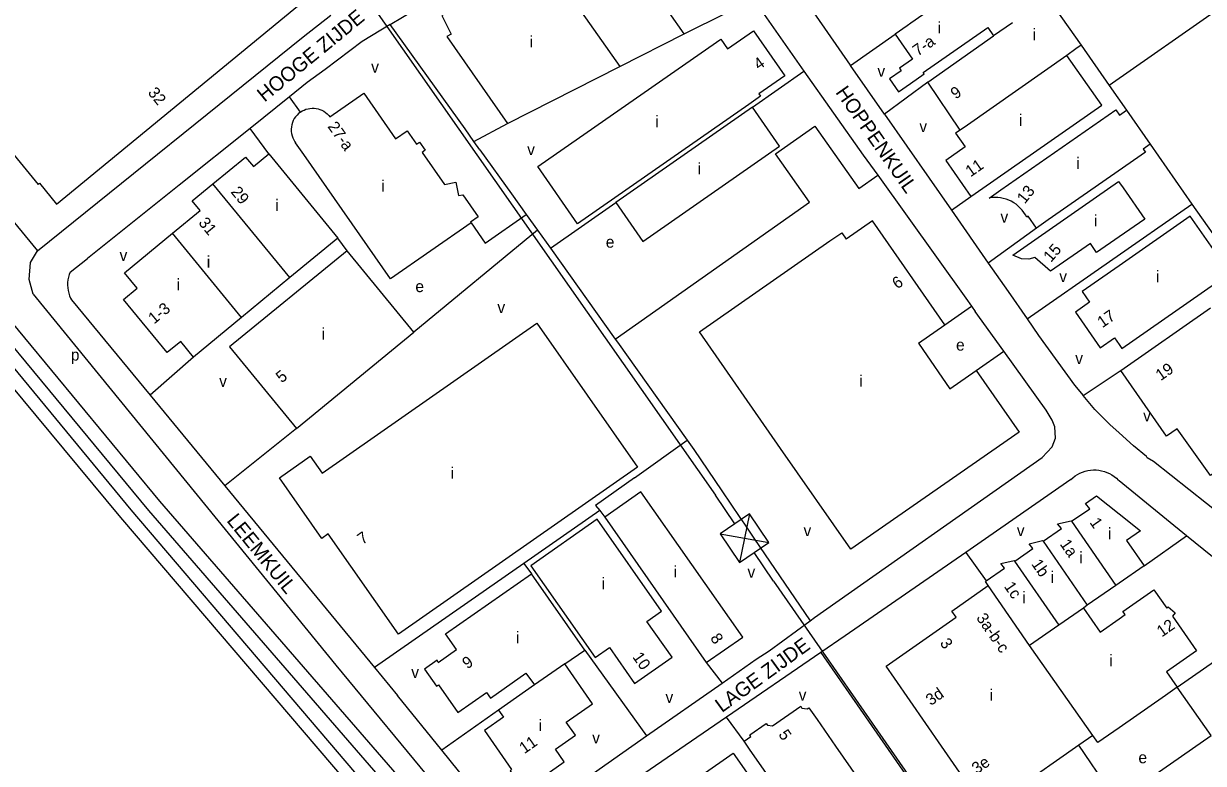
# Model space of a CAD drawing. Extents: x 156721 to 158827, y 386657 to 388950.
# Drawn here: x 156928.2 to 157336.1, y 387994 to 388249.8 of the extents above; entities that cross this region are included whole.
import ezdxf

# ---------------------------------------------------------------- set-up
doc = ezdxf.new("R2010")
doc.units = 0
for name, color, linetype in [('BLT_Basislijn', 7, 'Continuous'), ('BLT_Bebouwing', 7, 'Continuous'), ('BLT_Centroide', 7, 'Continuous'), ('BLT_Hoogspanningsmast_en_leidingen', 7, 'Continuous'), ('BLT_Huisnummer', 7, 'Continuous'), ('BLT_Huisnummer_reeks', 7, 'Continuous'), ('BLT_Onderverdeling_panden', 7, 'Continuous'), ('BLT_Spoorlijn', 7, 'Continuous'), ('BLT_Straatnaam', 7, 'Continuous')]:
    doc.layers.add(name, color=color, linetype=linetype)

msp = doc.modelspace()

# ---------------------------------------------------------------- linework, layer by layer
at = {"layer": 'BLT_Basislijn'}
for p, q in [((157181.81, 388256.38), (157197.97, 388233.43)), ((157342.19, 388255.43), (157303.53, 388228.38)), ((157156.54, 388246.26), (157171.21, 388253.53)), ((157214.08, 388235.38), (157229.53, 388246.22)), ((157293.8, 388242.31), (157303.53, 388228.38)), ((157225.82, 388218.52), (157214.08, 388235.38)), ((157180.18, 388220.88), (157197.97, 388233.43)), ((157197.97, 388233.43), (157218.52, 388204.37)), ((157240.87, 388229.61), (157225.82, 388218.52)), ((157303.53, 388228.38), (157309.5, 388219.84)), ((157020.19, 388224.52), (157006.55, 388213.59)), ((157023.9, 388219.23), (157020.19, 388224.52)), ((157083.93, 388209.08), (157095.54, 388215.31)), ((157225.82, 388218.52), (157248.98, 388185.32)), ((157006.55, 388213.59), (156982.02, 388193.93)), ((157012.98, 388204.79), (157006.55, 388213.59)), ((157085.98, 388206.23), (157083.93, 388209.08)), ((157317.68, 388208.11), (157332.16, 388187.41)), ((156904.22, 388206.2), (156933, 388171.26)), ((157085.98, 388206.23), (157096.92, 388190.96)), ((156882.19, 388197.04), (156975.19, 388084.73)), ((156982.02, 388193.93), (156950.34, 388168.56)), ((157096.92, 388190.96), (157102, 388183.86)), ((157248.98, 388185.32), (157255.75, 388190.07)), ((157110.34, 388172.18), (157132.95, 388187.99)), ((157275.16, 388147.74), (157332.16, 388187.41)), ((157332.16, 388187.41), (157351.14, 388160.27)), ((157102, 388183.86), (157105.89, 388178.43)), ((157248.98, 388185.32), (157261.74, 388167.03)), ((157105.89, 388178.43), (157063.13, 388143.09)), ((157105.89, 388178.43), (157110.34, 388172.18)), ((157278.39, 388179.09), (157261.74, 388167.03)), ((157040.03, 388171.28), (157036.9, 388175.64)), ((157110.34, 388172.18), (157132.77, 388140.76)), ((156944.29, 388163.93), (156950.34, 388168.56)), ((156931.5, 388156.24), (156995.39, 388077.95)), ((156944.73, 388154.35), (156971.92, 388121.35)), ((157246.71, 388145.66), (157255.9, 388152.1)), ((156986.97, 388134.54), (156971.92, 388121.35)), ((157257.58, 388129.9), (157267.08, 388136.5)), ((157294.55, 388121.21), (157306.95, 388129.58)), ((157306.95, 388129.58), (157307.54, 388129.89)), ((156971.92, 388121.35), (156997.81, 388089.95)), ((157022.55, 388109.84), (156997.81, 388089.95)), ((157139.45, 388092.71), (157157.63, 388105.84)), ((157139.45, 388092.71), (157125.94, 388083.22)), ((157290.3, 388092.17), (157253.94, 388066.99)), ((156997.81, 388089.95), (157049.56, 388027.17)), ((157169.66, 388088.25), (157175.89, 388079.07)), ((157306.95, 388091.75), (157306.68, 388091.97)), ((157330.23, 388072.76), (157306.95, 388091.75)), ((157127.41, 388081.49), (157101.18, 388063.19)), ((157125.94, 388083.22), (157127.41, 388081.49)), ((157127.41, 388081.49), (157129.11, 388079.17)), ((156995.39, 388077.95), (157036.15, 388028.01)), ((157175.89, 388079.07), (157177.49, 388076.7)), ((157177.49, 388076.7), (157180.71, 388071.95)), ((157180.71, 388071.95), (157182.66, 388069.07)), ((157315.6, 388062.38), (157330.23, 388072.76)), ((157353.28, 388053.95), (157330.23, 388072.76)), ((157182.66, 388069.07), (157200.14, 388043.27)), ((157253.94, 388066.99), (157212.31, 388038.16)), ((157253.94, 388066.99), (157261.02, 388057.14)), ((157101.18, 388063.19), (157049.56, 388027.17)), ((157101.18, 388063.19), (157103.8, 388059.53)), ((157327.07, 388020.36), (157362.69, 388045.37)), ((157212.31, 388038.16), (157203.8, 388032.33)), ((157122.2, 388033.18), (157143.6, 388003.53)), ((157203.8, 388032.33), (157171.21, 388010.02)), ((157203.8, 388032.33), (157240.15, 387980.09)), ((157036.15, 388028.01), (157169.06, 387867.32)), ((157049.56, 388027.17), (157057.48, 388017.55)), ((157164.2, 388028.86), (157169.69, 388021.79)), ((157143.6, 388003.53), (157169.69, 388021.79)), ((157338.76, 388003.71), (157327.07, 388020.36)), ((157072.83, 387998.56), (157057.48, 388017.55)), ((157092.39, 388012.46), (157072.83, 387998.56)), ((157171.21, 388010.02), (157109.44, 387967.74)), ((157177.3, 388001.69), (157171.21, 388010.02)), ((157104.5, 387976.17), (157143.6, 388003.53)), ((157090.57, 387976.6), (157072.83, 387998.56))]:
    msp.add_line(p, q, dxfattribs=at)
for points in [[(157054.94, 388249.56), (157067.74, 388257.09), (157078.57, 388262.26), (157088.23, 388267.49), (157145.85, 388296.83), (157148.06, 388297.3), (157150.99, 388297.47), (157153.2, 388296.54), (157155.52, 388294.2), (157180.29, 388258.56)], [(157197.86, 388258.78), (157198.32, 388258.14), (157213.99, 388235.5), (157214.08, 388235.38)], [(156933, 388171.26), (157024.89, 388245.27), (157034.44, 388252.69)], [(157054.94, 388249.56), (157045.3, 388243.68), (157032.46, 388233.97), (157026.3, 388229.42), (157020.19, 388224.52)], [(157083.93, 388209.08), (157080.85, 388213.38), (157054.94, 388249.56)], [(157132.77, 388140.76), (157199.97, 388188.11), (157188.21, 388204.81), (157201.78, 388214.37), (157216.99, 388192.78), (157223.52, 388197.38)], [(157218.52, 388204.37), (157223.52, 388197.38)], [(157223.52, 388197.38), (157253.92, 388154.87), (157255.9, 388152.1)], [(157082.92, 388180.95), (157087.8, 388173.95), (157102, 388183.86)], [(156931.5, 388156.24), (156930.1, 388161.39), (156930.61, 388167.25), (156933, 388171.26)], [(157261.74, 388167.03), (157268.62, 388157.17), (157275.16, 388147.74)], [(156944.29, 388163.93), (156943.96, 388163.06), (156943.7, 388162.16), (156943.52, 388161.25), (156943.41, 388160.32), (156943.39, 388159.39), (156943.45, 388158.45), (156943.58, 388157.53), (156943.8, 388156.62), (156944.09, 388155.74), (156944.46, 388154.88), (156944.73, 388154.35)], [(157255.9, 388152.1), (157257.24, 388150.23)], [(157267.08, 388136.5), (157257.24, 388150.23)], [(157275.16, 388147.74), (157279.15, 388141.99), (157291.59, 388124.77), (157294.55, 388121.21)], [(157132.77, 388140.76), (157133.55, 388139.69), (157157.63, 388105.84)], [(157200.14, 388043.27), (157201.7, 388044.41), (157280.41, 388099.77), (157283.84, 388103.46), (157284.96, 388106.42), (157284.8, 388110.41), (157283.78, 388112.74), (157281.7, 388116.1), (157267.08, 388136.5)], [(157306.95, 388108.35), (157303.79, 388111.21), (157298.56, 388116.38), (157294.55, 388121.21)], [(157157.63, 388105.84), (157159.96, 388102.56), (157169.66, 388088.25)], [(157343.34, 388079.1), (157318.8, 388098.44), (157316.67, 388099.68), (157316.49, 388100.1), (157311.93, 388103.84), (157306.95, 388108.35)], [(157290.3, 388092.17), (157291.01, 388092.81), (157291.78, 388093.4), (157292.58, 388093.91), (157293.43, 388094.36), (157294.32, 388094.74), (157295.23, 388095.04), (157296.16, 388095.27), (157297.11, 388095.41), (157298.07, 388095.48), (157299.03, 388095.47), (157299.98, 388095.38), (157300.93, 388095.2), (157301.86, 388094.95), (157302.76, 388094.63), (157303.63, 388094.23), (157304.47, 388093.76), (157305.26, 388093.22), (157306.01, 388092.61), (157306.68, 388091.97)], [(156975.19, 388084.73), (157094.16, 387947.52), (157166.18, 387865.29)], [(157169.69, 388021.79), (157181.46, 388030.1), (157185.99, 388032.98), (157200.14, 388043.27)]]:
    msp.add_lwpolyline(points, dxfattribs=at)
at = {"layer": 'BLT_Bebouwing'}
for p, q in [((157156.54, 388246.26), (157151.41, 388253.67)), ((157074.56, 388245.32), (157095.54, 388215.31)), ((157134.3, 388234.97), (157156.54, 388246.26)), ((157240.87, 388229.61), (157263.58, 388245.55)), ((157292.06, 388241.06), (157288.94, 388238.83)), ((157095.54, 388215.31), (157134.3, 388234.97)), ((157300.96, 388221.65), (157288.94, 388238.83)), ((157252.03, 388213.02), (157240.87, 388229.61)), ((157012.98, 388204.79), (157036.9, 388175.64)), ((156933.68, 388194.59), (156939.56, 388187.44)), ((157270.21, 388169.74), (157306.79, 388195.19)), ((157306.79, 388195.19), (157308.33, 388192.98)), ((157331.5, 388183.23), (157306.95, 388166.09)), ((157345.25, 388163.53), (157331.5, 388183.23)), ((157036.9, 388175.64), (157020.3, 388161.98)), ((157063.13, 388143.09), (157040.03, 388171.28)), ((157306.95, 388166.09), (157294.19, 388157.18)), ((157020.3, 388161.98), (157003.59, 388148.22)), ((157307.54, 388129.89), (157338.61, 388151.54)), ((157022.55, 388109.84), (157063.13, 388143.09)), ((157237.62, 388139.3), (157239.12, 388137.14)), ((157122.2, 388033.18), (157103.8, 388059.53)), ((157315.6, 388062.38), (157306.95, 388056.35)), ((157305.84, 388055.57), (157295.98, 388048.69)), ((157306.95, 388056.35), (157305.84, 388055.57)), ((157295.98, 388048.69), (157294.62, 388047.74)), ((157115.33, 388028.48), (157122.2, 388033.18)), ((157104.83, 388021.14), (157092.39, 388012.46)), ((157297.94, 388003.66), (157293.07, 388000.27)), ((157299.62, 388001.23), (157297.94, 388003.66)), ((157306.95, 388006.35), (157299.62, 388001.23)), ((157306.15, 387981), (157338.76, 388003.71)), ((157306.15, 387981), (157293.07, 388000.27))]:
    msp.add_line(p, q, dxfattribs=at)
for points in [[(156939.56, 388187.44), (157028.11, 388260.24), (157022.23, 388267.38), (157022.66, 388267.73)], [(157113.32, 388264.95), (157106.8, 388261.68), (157103.55, 388268.11), (157089.99, 388261.26), (157089.63, 388261.95), (157084.48, 388259.33), (157084.8, 388258.65), (157072.86, 388252.59), (157076.09, 388246.18), (157074.56, 388245.32)], [(157258.66, 388266.55), (157234.95, 388250), (157233.64, 388249.08), (157229.53, 388246.22)], [(157282.34, 388258.71), (157293.8, 388242.31)], [(157171.55, 388241.12), (157180.54, 388247.36), (157191.37, 388231.8), (157182.4, 388225.55)], [(157229.53, 388246.22), (157235.57, 388237.57), (157231.01, 388234.39), (157231.64, 388233.49), (157227.61, 388230.68), (157230.68, 388226.28), (157234.79, 388229.14), (157239.53, 388232.45), (157239.24, 388232.88), (157261.55, 388248.45), (157263.58, 388245.55)], [(157182.4, 388225.55), (157183.01, 388224.68), (157178.91, 388221.83), (157119.75, 388180.62), (157106, 388200.43), (157165.12, 388241.59), (157169.23, 388244.45), (157171.55, 388241.12)], [(157293.8, 388242.31), (157292.06, 388241.06)], [(157023.9, 388219.23), (157024.5, 388219.61), (157025.16, 388219.94), (157025.83, 388220.2), (157026.56, 388220.4), (157027.22, 388220.51), (157027.94, 388220.57), (157028.66, 388220.56), (157029.36, 388220.48), (157030.02, 388220.34), (157030.68, 388220.13), (157031.34, 388219.85), (157032, 388219.5), (157032.64, 388219.05), (157033.18, 388218.6), (157033.7, 388218.07), (157034.12, 388217.54), (157045.89, 388225.77), (157056.84, 388209.99), (157060.79, 388212.75), (157064.01, 388208.1), (157065.11, 388208.84), (157067.05, 388206.07), (157065.97, 388205.3), (157073.69, 388194.21), (157077.63, 388194.97), (157078.6, 388190.34), (157080.11, 388190.65), (157085.4, 388183.05), (157082.74, 388181.2), (157082.92, 388180.95)], [(157023.9, 388219.23), (157023.3, 388218.75), (157022.74, 388218.21), (157022.24, 388217.62), (157021.81, 388216.98), (157021.45, 388216.3), (157021.15, 388215.58), (157020.94, 388214.84), (157020.8, 388214.08), (157020.74, 388213.3), (157020.76, 388212.53), (157020.86, 388211.77), (157021.03, 388211.01), (157021.29, 388210.28), (157021.62, 388209.58), (157022.02, 388208.92), (157022.22, 388208.64)], [(157180.18, 388220.88), (157132.95, 388187.99)], [(157132.95, 388187.99), (157142.35, 388174.51), (157189.57, 388207.4), (157180.18, 388220.88)], [(157255.75, 388190.07), (157259.85, 388192.94), (157300.96, 388221.65)], [(157261.99, 388189.49), (157266.09, 388192.36), (157305.78, 388220.06), (157307.1, 388218.17), (157309.5, 388219.84)], [(157309.5, 388219.84), (157317.68, 388208.11)], [(156917.02, 388213.95), (156933.23, 388194.21), (156933.68, 388194.59)], [(157252.03, 388213.02), (157250.42, 388211.89), (157253.75, 388207.23), (157247.04, 388202.52), (157255.75, 388190.07)], [(157082.92, 388180.95), (157055.08, 388161.53), (157025.09, 388204.54), (157022.22, 388208.64)], [(157317.68, 388208.11), (157315.29, 388206.44), (157316.06, 388205.33), (157282.49, 388181.95), (157278.39, 388179.09)], [(156993.67, 388194.38), (157004.93, 388203.66), (157007.67, 388200.39), (157012.98, 388204.79)], [(156986.54, 388188.5), (156993.67, 388194.38)], [(157308.33, 388192.98), (157315.81, 388182.24), (157306.95, 388176.08)], [(156979.68, 388177.35), (156989.23, 388185.22), (156986.54, 388188.5)], [(157275.02, 388182.86), (157274.57, 388183.73), (157274.05, 388184.55), (157273.46, 388185.33), (157272.81, 388186.06), (157272.1, 388186.74), (157271.34, 388187.35), (157270.53, 388187.9), (157269.68, 388188.38), (157268.79, 388188.79), (157267.87, 388189.13), (157266.93, 388189.39), (157265.97, 388189.57), (157264.99, 388189.68), (157264.02, 388189.7), (157263.04, 388189.64), (157262.07, 388189.51), (157261.99, 388189.49)], [(157278.39, 388179.09), (157275.52, 388183.21), (157275.02, 388182.86)], [(157246.71, 388145.66), (157221.69, 388181.58), (157212.64, 388175.28)], [(156986.97, 388134.54), (156982.6, 388139.89), (156977.9, 388136.05), (156962.78, 388154.47), (156967.47, 388158.3), (156963.06, 388163.66), (156979.68, 388177.35)], [(157189.94, 388102.89), (157161.84, 388143.24), (157206.97, 388174.67), (157211.08, 388177.53), (157212.64, 388175.28)], [(157306.95, 388176.08), (157299.2, 388170.68), (157297.02, 388173.8), (157283.26, 388164.17), (157277.84, 388168.99), (157275.81, 388168.34), (157273.27, 388168.48), (157270.21, 388169.74)], [(157040.03, 388171.28), (156999.45, 388138.02), (157022.55, 388109.84)], [(157306.95, 388138.91), (157307.95, 388137.49), (157345.25, 388163.53)], [(157294.19, 388157.18), (157296.77, 388153.49), (157291.85, 388150.06), (157300.45, 388137.74), (157305.37, 388141.18), (157306.95, 388138.91)], [(157003.59, 388148.22), (156986.97, 388134.54)], [(157027.33, 388100.26), (157031.45, 388094.36), (157105.65, 388146.19), (157140.44, 388096.39), (157057.84, 388038.7), (157033.56, 388073.34), (157031.35, 388071.79), (157016.65, 388092.76), (157027.33, 388100.26)], [(157237.62, 388139.3), (157246.71, 388145.66)], [(157239.12, 388137.14), (157248.5, 388123.59), (157257.58, 388129.9)], [(157257.58, 388129.9), (157272.43, 388108.58), (157214.23, 388068.1), (157189.94, 388102.89)], [(157356.43, 388106.06), (157338.52, 388093.57), (157327.06, 388109.73), (157323.39, 388107.18), (157307.54, 388129.89)], [(157164.2, 388028.86), (157176.83, 388037.68), (157141.58, 388087.88), (157129.11, 388079.17)], [(157290.54, 388077.72), (157296.83, 388082.08), (157295.29, 388083.86), (157299.13, 388086.55), (157306.95, 388080.36)], [(157306.95, 388080.36), (157314.38, 388074.48), (157309.55, 388071.08), (157315.6, 388062.38)], [(157125.78, 388030.63), (157130.79, 388034.14), (157139.41, 388021.65), (157152.49, 388030.77), (157143.7, 388043.14), (157148.72, 388046.64), (157126.48, 388078.49), (157103.62, 388062.29)], [(157129.11, 388079.17), (157164.2, 388028.86)], [(157280.68, 388070.85), (157287, 388075.21), (157285.7, 388076.8), (157290.35, 388077.92), (157290.54, 388077.72)], [(157270.87, 388063.99), (157277.17, 388068.37), (157275.86, 388069.93), (157280.52, 388071.05), (157280.68, 388070.85)], [(157261.02, 388057.14), (157267.31, 388061.49), (157266.03, 388063.11), (157270.67, 388064.2), (157270.87, 388063.99)], [(157071.59, 388028.95), (157077.83, 388033.35), (157074.04, 388038.77), (157103.8, 388059.53)], [(157103.62, 388062.29), (157125.78, 388030.63)], [(157260.93, 387977.89), (157245.61, 388000), (157229.3, 388023.54), (157226.45, 388027.65), (157250.63, 388044.54), (157249.11, 388046.71), (157261.73, 388055.53)], [(157261.73, 388055.53), (157260.74, 388056.95), (157261.02, 388057.14)], [(157306.95, 388044), (157309.05, 388045.45), (157308.29, 388046.54), (157319.03, 388054.03), (157323.48, 388047.64), (157323.93, 388048.17), (157326.37, 388046.1), (157325.37, 388044.92), (157333.72, 388032.92), (157323.35, 388025.66), (157327.07, 388020.36)], [(157294.62, 388047.74), (157300.38, 388039.44), (157306.95, 388044)], [(157071.59, 388028.95), (157071.18, 388029.7), (157066.8, 388026.64), (157070.92, 388020.72), (157071.61, 388021.2)], [(157115.85, 388008.3), (157124.89, 388014.58), (157115.33, 388028.48)], [(157071.61, 388021.2), (157078.35, 388011.59), (157088.23, 388018.51), (157089.58, 388016.59), (157101.85, 388025.19), (157104.83, 388021.14)], [(157327.07, 388020.36), (157322.97, 388017.51), (157306.95, 388006.35)], [(157092.39, 388012.46), (157094.11, 388009.99), (157087.55, 388005.42), (157096.89, 387991.93), (157096.38, 387991.5), (157101.36, 387984.23), (157101.56, 387984.19), (157108.81, 387989.27), (157108.4, 387989.85), (157115.14, 387994.59), (157112.1, 387998.97), (157119.01, 388003.77), (157115.85, 388008.3)], [(157177.3, 388001.69), (157179.69, 388003.34), (157179.28, 388003.91), (157184.93, 388007.86), (157185.35, 388007.27), (157187.15, 388006.98), (157196.91, 388013.77), (157197.32, 388013.14), (157199.1, 388012.91), (157199.69, 388013.26), (157202.55, 388009.16)], [(157202.55, 388009.16), (157208.92, 388000), (157219.55, 387984.74), (157223.61, 387987.58), (157232.26, 387975.15)], [(157207.74, 387957.97), (157179.18, 387998.98), (157178.48, 388000), (157177.3, 388001.69)]]:
    msp.add_lwpolyline(points, dxfattribs=at)
msp.add_lwpolyline([(157173.58, 387997.58), (157186.78, 387978.67), (157162.4, 387961.64), (157175.57, 387942.78), (157155.62, 387928.88), (157138.87, 387952.87), (157132.32, 387948.3), (157121.58, 387963.7), (157128.3, 387968.4), (157129.48, 387966.8)], close=True, dxfattribs=at)
at = {"layer": 'BLT_Hoogspanningsmast_en_leidingen'}
for p, q in [((157043.67, 388263.27), (157167.45, 388086.75)), ((157174.11, 388076.84), (157167.45, 388086.75)), ((157179.22, 388080.28), (157175.67, 388063.5)), ((157169.01, 388073.41), (157185.89, 388070.38)), ((157187.44, 388057.04), (157180.78, 388066.94)), ((157187.44, 388057.04), (157303.34, 387890.44))]:
    msp.add_line(p, q, dxfattribs=at)
msp.add_lwpolyline([(157175.67, 388063.5), (157185.89, 388070.38), (157179.22, 388080.28), (157169.01, 388073.41)], close=True, dxfattribs=at)
at = {"layer": 'BLT_Onderverdeling_panden'}
for p, q in [((157113.32, 388264.95), (157134.3, 388234.97)), ((157020.3, 388161.98), (156993.67, 388194.38)), ((157003.59, 388148.22), (156979.68, 388177.35)), ((157290.54, 388077.72), (157305.84, 388055.57)), ((157280.68, 388070.85), (157295.98, 388048.69)), ((157276.03, 388034.84), (157261.73, 388055.53)), ((157294.62, 388047.74), (157286.12, 388041.84)), ((157286.12, 388041.84), (157276.03, 388034.84)), ((157297.94, 388003.66), (157276.03, 388034.84)), ((157115.33, 388028.48), (157104.83, 388021.14)), ((157293.07, 388000.27), (157260.96, 387977.91))]:
    msp.add_line(p, q, dxfattribs=at)
for points in [[(157270.15, 388250.09), (157263.58, 388245.55)], [(157288.94, 388238.83), (157254.51, 388214.75), (157252.03, 388213.02)], [(157270.87, 388063.99), (157270.84, 388063.97), (157286.12, 388041.84)]]:
    msp.add_lwpolyline(points, dxfattribs=at)
at = {"layer": 'BLT_Spoorlijn'}
for points in [[(156869.24, 388190.25), (156961.7, 388079.1)], [(156881.31, 388190.25), (156971.42, 388081.45)], [(156877.78, 388187.6), (156965.23, 388081.75)], [(156965.23, 388081.75), (157070.65, 387958.09)], [(156971.42, 388081.45), (157090.38, 387944.24)], [(156961.7, 388079.1), (157078.6, 387942.18)]]:
    msp.add_lwpolyline(points, dxfattribs=at)

# ---------------------------------------------------------------- texts
at = {"layer": 'BLT_Centroide'}
for s, p in [('i', (157244.22, 388246.41)), ('i', (157277.02, 388244.06)), ('i', (157103.2, 388241.56)), ('v', (157048.38, 388232.84)), ('v', (157223.41, 388231.43)), ('i', (157272.36, 388214.44)), ('i', (157146.56, 388214)), ('v', (157237.9, 388212.32)), ('v', (157102.32, 388204.33)), ('i', (157292.12, 388199.56)), ('i', (157161.27, 388197.69)), ('i', (157051.83, 388191.7)), ('i', (157015.28, 388185.03)), ('v', (157265.94, 388180.99)), ('i', (157298.32, 388179.69)), ('e', (157129.5, 388172.34)), ('v', (156961.4, 388167.77)), ('i', (156991.55, 388165.47)), ('i', (156981.08, 388157.6)), ('v', (157286.28, 388160.44)), ('i', (157319.72, 388160.38)), ('e', (157063.67, 388156.98)), ('v', (157092.02, 388149.74)), ('i', (157031.29, 388140.56)), ('e', (157250.59, 388136.75)), ('p', (156944.55, 388133.3)), ('v', (157291.81, 388132.12)), ('v', (156995.83, 388124.22)), ('i', (157217.12, 388124.27)), ('v', (157315.27, 388112.27)), ('i', (157075.84, 388092.44)), ('v', (157197.87, 388072.6)), ('v', (157271.61, 388072.6)), ('i', (157303.06, 388071.5)), ('i', (157293.25, 388063.2)), ('i', (157152.97, 388058.31)), ('v', (157178.49, 388058.24)), ('i', (157283.33, 388056.44)), ('i', (157128.05, 388054.23)), ('i', (157273.44, 388049.41)), ('i', (157098.41, 388035.56)), ('i', (157303.62, 388027.62)), ('v', (157062.25, 388023.57)), ('v', (157196.2, 388015.76)), ('i', (157262.2, 388015.66)), ('v', (157150.14, 388014.94)), ('i', (157106.22, 388005.17)), ('v', (157124.8, 388000.92)), ('e', (157313.65, 387994.08))]:
    msp.add_text(s, height=4, dxfattribs=at).set_placement(p)
at = {"layer": 'BLT_Huisnummer'}
for s, rotation, p in [('4', 34.8869, (157182.38, 388233.62)), ('32', 308.8459, (156970.97, 388225.88)), ('9', 34.901, (157250.45, 388223.51)), ('11', 34.9423, (157255.6, 388196.62)), ('29', 309.3959, (156999.65, 388191.54)), ('13', 50.9842, (157274.34, 388187.26)), ('31', 309.3883, (156988.46, 388180.87)), ('15', 48.9831, (157283.4, 388167.05)), ('6', 34.8488, (157230.25, 388157.88)), ('17', 34.9185, (157301.18, 388144.45)), ('5', 39.3388, (157017.46, 388125.38)), ('19', 34.8707, (157321.32, 388126.14)), ('1', 304.6262, (157296.62, 388077.33)), ('7', 35.032, (157045.37, 388069.5)), ('1a', 304.6475, (157286.32, 388069.85)), ('1b', 304.6475, (157276.47, 388062.97)), ('1c', 304.6475, (157267.02, 388055.2)), ('12', 35.0002, (157321.73, 388037.53)), ('8', 305.0746, (157165.43, 388037.3)), ('9', 35.0478, (157081.62, 388026.5)), ('10', 305.0414, (157138.57, 388030.8)), ('11', 35.0478, (157101.33, 387997.16)), ('5', 304.8507, (157189.01, 388003.99))]:
    msp.add_text(s, height=4, rotation=rotation, dxfattribs=at).set_placement(p)
at = {"layer": 'BLT_Huisnummer_reeks'}
for s, rotation, p in [('7-a', 34.9108, (157237.36, 388238.4)), ('27-a', 305.4036, (157033.15, 388214.22)), ('1-3', 39.3888, (156973.33, 388145.75)), ('3a-b-c', 304.6475, (157257.41, 388044.32)), ('3', 304.6475, (157244.82, 388035.63)), ('3d', 34.8429, (157241.87, 388013.83)), ('3e', 34.8429, (157257.78, 387990.19))]:
    msp.add_text(s, height=4, rotation=rotation, dxfattribs=at).set_placement(p)
at = {"layer": 'BLT_Straatnaam'}
for s, rotation, p in [('HOOGE ZIJDE', 39.4185, (157011.5, 388222.49)), ('HOPPENKUIL', 304.9242, (157208.74, 388226.05)), ('LEEMKUIL', 309.1526, (156998.21, 388077.87)), ('LAGE ZIJDE', 35.9675, (157169.62, 388011.39))]:
    msp.add_text(s, height=5, rotation=rotation, dxfattribs=at).set_placement(p)

doc.saveas('drawing.dxf')
